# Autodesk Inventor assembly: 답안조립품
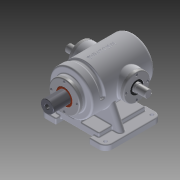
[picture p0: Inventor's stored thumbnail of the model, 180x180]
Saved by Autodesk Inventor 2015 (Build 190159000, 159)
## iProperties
Created: 2015-10
Part Number: 답안조립품
Document SubType Name: Assembly
Designer: youjin07
Mass: 9437.34 g
Surface Area: 4327.34 cm^2
Volume: 2315.26 cm^3
Density: 4.07615 g/cm^3
Author: youjin07
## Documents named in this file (13)
- C:\Users\youjin07\Desktop\351019V1016\답안조립품.iam
- C:\Users\youjin07\Desktop\351019V1016\본체.ipt
- C:\Users\youjin07\Desktop\351019V1016\슬라이드 커버.ipt
- C:\Users\youjin07\Desktop\351019V1016\축 커버.ipt
- C:\Users\youjin07\Desktop\351019V1016\M4x0.7.ipt
- C:\Users\youjin07\Desktop\351019V1016\오일실.ipt
- 오일실.ipt
- C:\Users\youjin07\Desktop\351019V1016\부시.ipt
- C:\Users\youjin07\Desktop\351019V1016\베어링 6205.ipt
- 베어링 6205.ipt
- C:\Users\youjin07\Desktop\351019V1016\편심축.ipt
- C:\Users\youjin07\Desktop\351019V1016\가변스프링.ipt
- C:\Users\youjin07\Desktop\351019V1016\슬라이드.ipt
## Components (13 placed, 2 different names)
1. 가변스프링:1 — Mate:22, Mate:23, Mate:24, Mate:25
2. M4x0.7:1 — Insert:1
3. M4x0.7:4
4. M4x0.7:5
5. M4x0.7:6
6. M4x0.7:3 — Insert:2
7. M4x0.7:7
8. M4x0.7:8
9. M4x0.7:9
10. M4x0.7:2 — Insert:3
11. M4x0.7:10
12. M4x0.7:11
13. M4x0.7:12
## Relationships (7: Mate 4, Insert 3)
- Insert:1: M4x0.7:1
- Insert:2: M4x0.7:3
- Insert:3: M4x0.7:2
- Mate:22: 가변스프링:1
- Mate:23: 가변스프링:1
- Mate:24: 가변스프링:1
- Mate:25: 가변스프링:1
